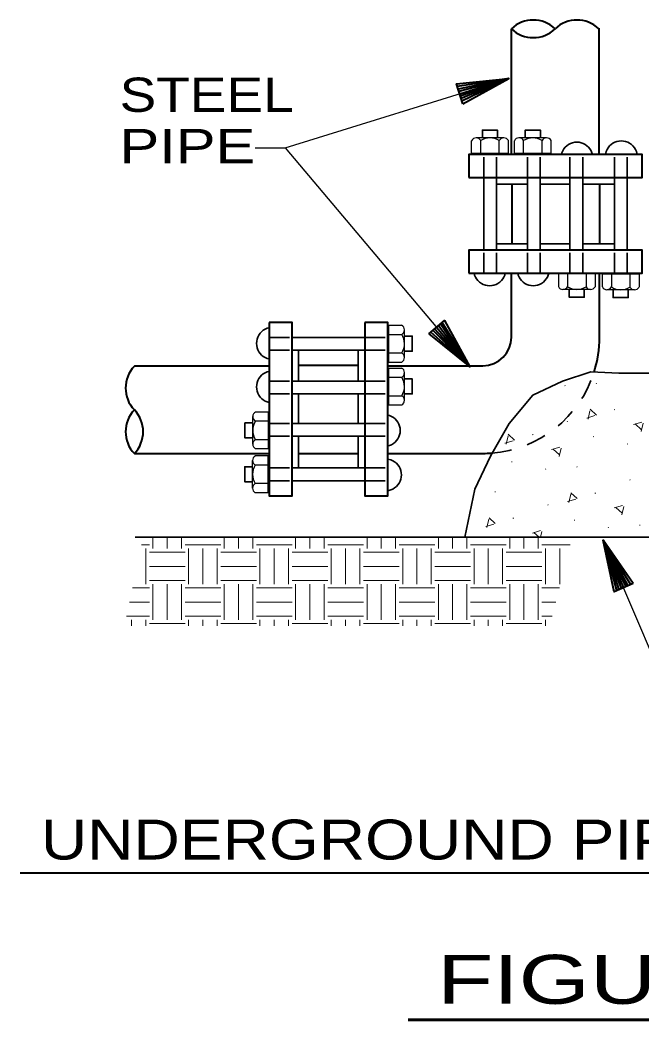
# Model space of a CAD drawing. Extents: x 55 to 190, y 198 to 264.
# Drawn here: x 91.18 to 95.8, y 210.74 to 218.16 of the extents above; entities that cross this region are included whole.
import ezdxf
from ezdxf.enums import TextEntityAlignment as Align

# ---------------------------------------------------------------- set-up
doc = ezdxf.new("R2010")
doc.units = 0
doc.header["$LTSCALE"] = 0.1
doc.linetypes.add('SHORT_DASHED', pattern=[2.7, 1.5, -1.2])
doc.layers.add('2', color=7, linetype='Continuous', lineweight=40)

msp = doc.modelspace()

# ---------------------------------------------------------------- linework, layer by layer
at = {"layer": '2'}
for p, q in [((94.8281, 217.1625), (94.8281, 218.0939)), ((95.4787, 217.1625), (95.4787, 218.0994)), ((94.8101, 217.7242), (94.4283, 217.6647)), ((94.8101, 217.7242), (94.4391, 217.629)), ((94.4447, 217.6107), (94.8101, 217.7242)), ((94.8101, 217.7242), (94.4502, 217.5938)), ((94.8101, 217.7242), (94.4548, 217.5774)), ((94.8101, 217.7242), (94.4616, 217.557)), ((94.832, 216.94), (94.832, 216.4995)), ((95.4832, 216.4995), (95.4832, 216.94)), ((94.8281, 215.806), (94.8281, 216.2815)), ((95.4816, 215.806), (95.4816, 216.2815)), ((94.5193, 215.5867), (94.2455, 215.8568)), ((94.5193, 215.5867), (94.259, 215.8674)), ((94.2725, 215.879), (94.5193, 215.5867)), ((94.5193, 215.5867), (94.2873, 215.8912)), ((94.5193, 215.5867), (94.3158, 215.9153)), ((94.5193, 215.5867), (94.2296, 215.8425)), ((92.0322, 215.5943), (93.0318, 215.5943)), ((93.6904, 215.5949), (93.2498, 215.5949)), ((93.9129, 215.5943), (94.6164, 215.5943)), ((92.0322, 214.9435), (93.0318, 214.9435)), ((93.2498, 214.9437), (93.6904, 214.9437)), ((93.9129, 214.9435), (94.6164, 214.9435)), ((95.6607, 213.947), (95.5094, 214.2987)), ((95.5094, 214.2987), (95.6927, 213.9605)), ((95.5094, 214.2987), (95.6086, 213.9251)), ((95.5094, 214.2987), (95.643, 213.9399)), ((95.5094, 214.2987), (95.6769, 213.9544)), ((95.5094, 214.2987), (95.7123, 213.9695)), ((91.1842, 211.8314), (100.5701, 211.8314))]:
    msp.add_line(p, q, dxfattribs=at)
at = {"layer": '2', "lineweight": 25}
for p, q in [((94.5328, 217.1694), (94.5328, 217.2636)), ((94.7712, 217.285), (94.5669, 217.285)), ((94.6008, 217.1694), (94.6008, 217.2644)), ((94.7379, 217.1694), (94.7379, 217.2644)), ((94.8056, 217.1694), (94.8056, 217.2644)), ((94.8506, 217.1694), (94.8506, 217.2636)), ((95.089, 217.285), (94.8847, 217.285)), ((94.9186, 217.1694), (94.9186, 217.2644)), ((95.0556, 217.1694), (95.0556, 217.2644)), ((95.1233, 217.1694), (95.1233, 217.2644)), ((93.1511, 217.2112), (94.5193, 215.5867)), ((94.8056, 217.1694), (94.5328, 217.1694)), ((95.1233, 217.1694), (94.8506, 217.1694)), ((95.4493, 216.2754), (95.1765, 216.2754)), ((95.1765, 216.2754), (95.1765, 216.1812)), ((95.2445, 216.2754), (95.2445, 216.1804)), ((95.3816, 216.2754), (95.3816, 216.1804)), ((95.4493, 216.2754), (95.4493, 216.1804)), ((95.775, 216.2735), (95.5022, 216.2735)), ((95.5022, 216.2735), (95.5022, 216.1793)), ((95.5702, 216.2735), (95.5702, 216.1785)), ((95.7073, 216.2735), (95.7073, 216.1785)), ((95.775, 216.2735), (95.775, 216.1785)), ((95.4149, 216.1597), (95.2107, 216.1597)), ((95.7406, 216.1579), (95.5364, 216.1579)), ((93.9198, 215.6213), (93.9198, 215.8941)), ((93.9198, 215.8941), (94.014, 215.8941)), ((94.0354, 215.6557), (94.0354, 215.86)), ((93.9198, 215.8261), (94.0148, 215.8261)), ((93.9198, 215.6891), (94.0148, 215.6891)), ((93.9198, 215.6213), (94.0148, 215.6213)), ((93.9198, 215.3036), (93.9198, 215.5763)), ((93.9198, 215.5763), (94.014, 215.5763)), ((93.9198, 215.5083), (94.0148, 215.5083)), ((94.0354, 215.338), (94.0354, 215.5422)), ((93.9198, 215.3713), (94.0148, 215.3713)), ((93.9198, 215.3036), (94.0148, 215.3036)), ((92.9101, 215.012), (92.9101, 215.2162)), ((93.0257, 215.2504), (92.9315, 215.2504)), ((93.0257, 214.9776), (93.0257, 215.2504)), ((93.0257, 215.1824), (92.9308, 215.1824)), ((93.0257, 215.0453), (92.9308, 215.0453)), ((93.0257, 214.9776), (92.9308, 214.9776)), ((92.9083, 214.6863), (92.9083, 214.8905)), ((93.0239, 214.9247), (92.9297, 214.9247)), ((93.0239, 214.6519), (93.0239, 214.9247)), ((93.0239, 214.8567), (92.9289, 214.8567)), ((93.0239, 214.7196), (92.9289, 214.7196)), ((93.0239, 214.6519), (92.9289, 214.6519))]:
    msp.add_line(p, q, dxfattribs=at)
at = {"layer": '2', "linetype": 'SHORT_DASHED', "lineweight": 35}
for p, q in [((94.6238, 216.9916), (94.6238, 217.1625)), ((94.7183, 216.9916), (94.7183, 217.1625)), ((94.9471, 216.9916), (94.9471, 217.1625)), ((95.0416, 216.9916), (95.0416, 217.1625)), ((95.2623, 216.9916), (95.2623, 217.1625)), ((95.3567, 216.9916), (95.3567, 217.1625)), ((95.5917, 216.9916), (95.5917, 217.1625)), ((95.6861, 216.9916), (95.6861, 217.1625)), ((94.6238, 216.282), (94.6238, 216.4529)), ((94.7183, 216.282), (94.7183, 216.4529)), ((94.9471, 216.282), (94.9471, 216.4529)), ((95.0416, 216.282), (95.0416, 216.4529)), ((95.2623, 216.282), (95.2623, 216.4529)), ((95.3567, 216.282), (95.3567, 216.4529)), ((95.5917, 216.282), (95.5917, 216.4529)), ((95.6861, 216.282), (95.6861, 216.4529)), ((93.0324, 215.8031), (93.2033, 215.8031)), ((93.742, 215.8031), (93.9129, 215.8031)), ((93.0324, 215.7086), (93.2033, 215.7086)), ((93.742, 215.7086), (93.9129, 215.7086)), ((93.0324, 215.4798), (93.2033, 215.4798)), ((93.742, 215.4798), (93.9129, 215.4798)), ((93.0324, 215.3853), (93.2033, 215.3853)), ((93.742, 215.3853), (93.9129, 215.3853)), ((93.0324, 215.1646), (93.2033, 215.1646)), ((93.742, 215.1646), (93.9129, 215.1646)), ((93.0324, 215.0702), (93.2033, 215.0702)), ((93.742, 215.0702), (93.9129, 215.0702)), ((93.0324, 214.8352), (93.2033, 214.8352)), ((93.742, 214.8352), (93.9129, 214.8352)), ((93.0324, 214.7408), (93.2033, 214.7408)), ((93.742, 214.7408), (93.9129, 214.7408))]:
    msp.add_line(p, q, dxfattribs=at)
at = {"layer": '2', "lineweight": 35}
for p, q in [((94.6238, 216.4524), (94.6238, 216.9916)), ((94.7183, 216.4524), (94.7183, 216.9916)), ((94.9471, 216.4524), (94.9471, 216.9916)), ((95.0416, 216.4524), (95.0416, 216.9916)), ((95.2623, 216.9916), (95.2623, 216.4524)), ((95.3567, 216.9916), (95.3567, 216.4524)), ((95.5917, 216.9916), (95.5917, 216.4524)), ((95.6861, 216.9916), (95.6861, 216.4524)), ((94.9463, 216.9403), (94.7183, 216.9403)), ((95.2625, 216.9403), (95.0413, 216.9403)), ((95.5917, 216.9403), (95.3575, 216.9403)), ((94.7183, 216.4979), (94.9463, 216.4979)), ((95.0413, 216.4979), (95.2625, 216.4979)), ((95.3575, 216.4979), (95.5917, 216.4979)), ((93.2027, 215.8031), (93.742, 215.8031)), ((93.2027, 215.7086), (93.742, 215.7086)), ((93.2483, 215.7086), (93.2483, 215.4806)), ((93.6906, 215.4806), (93.6906, 215.7086)), ((93.2027, 215.4798), (93.742, 215.4798)), ((93.2027, 215.3853), (93.742, 215.3853)), ((93.2483, 215.3856), (93.2483, 215.1644)), ((93.6906, 215.1644), (93.6906, 215.3856)), ((93.742, 215.1646), (93.2027, 215.1646)), ((93.742, 215.0702), (93.2027, 215.0702)), ((93.2483, 215.0694), (93.2483, 214.8352)), ((93.6906, 214.8352), (93.6906, 215.0694)), ((93.742, 214.8352), (93.2027, 214.8352)), ((93.742, 214.7408), (93.2027, 214.7408)), ((92.0375, 214.3211), (98.441, 214.3211))]:
    msp.add_line(p, q, dxfattribs=at)
at = {"layer": '2', "lineweight": 13}
for p, q in [((95.2271, 215.4443), (95.2234, 215.4478)), ((95.4583, 215.4652), (95.4573, 215.4602)), ((95.4107, 215.2591), (95.3964, 215.1972)), ((95.4594, 215.2276), (95.4131, 215.271)), ((95.5898, 215.2668), (95.5956, 215.2686)), ((95.3871, 215.2049), (95.448, 215.2236)), ((95.2416, 215.1787), (95.2429, 215.1837)), ((95.7946, 215.176), (95.7337, 215.1575)), ((95.7451, 215.1617), (95.7917, 215.1186)), ((95.7898, 215.1064), (95.8041, 215.1683)), ((94.7799, 215.0194), (94.8408, 215.0379)), ((94.8032, 215.0736), (94.7889, 215.0117)), ((94.8519, 215.0416), (94.8053, 215.085)), ((94.9823, 215.0813), (94.9884, 215.0832)), ((95.4403, 215.0678), (95.4353, 215.0662)), ((95.1874, 214.9903), (95.1265, 214.9718)), ((95.1376, 214.9757), (95.1842, 214.9326)), ((95.1821, 214.921), (95.1964, 214.9826)), ((95.6917, 215.0112), (95.6877, 215.0149)), ((94.8331, 214.8821), (94.8281, 214.8805)), ((95.0842, 214.8252), (95.0802, 214.8289)), ((95.3157, 214.8466), (95.3144, 214.8413)), ((95.7065, 214.7455), (95.7076, 214.7506)), ((94.7079, 214.6611), (94.7066, 214.6559)), ((95.2445, 214.586), (95.3054, 214.6045)), ((95.2681, 214.6402), (95.2538, 214.5786)), ((95.3162, 214.6088), (95.2699, 214.6519)), ((95.4469, 214.6477), (95.453, 214.6495)), ((95.0987, 214.5598), (95.1001, 214.5651)), ((95.6517, 214.5569), (95.5911, 214.5384)), ((95.6022, 214.5429), (95.6485, 214.4995)), ((95.647, 214.4876), (95.6613, 214.5495)), ((94.6603, 214.4548), (94.646, 214.3929)), ((94.7087, 214.4227), (94.6622, 214.4661)), ((94.8397, 214.4622), (94.8458, 214.464)), ((95.2975, 214.4487), (95.2924, 214.4471)), ((94.6373, 214.4003), (94.6979, 214.4188)), ((95.0445, 214.3712), (94.9839, 214.3526)), ((95.5485, 214.3921), (95.5446, 214.3958)), ((95.7803, 214.4135), (95.7793, 214.4082)), ((92.1698, 214.2375), (92.1698, 214.3246)), ((92.2756, 214.2375), (92.2756, 214.3246)), ((92.3815, 214.2375), (92.3815, 214.3246)), ((92.699, 214.2375), (92.699, 214.3246)), ((92.8048, 214.2375), (92.8048, 214.3246)), ((92.9106, 214.2375), (92.9106, 214.3246)), ((93.2281, 214.2375), (93.2281, 214.3246)), ((93.334, 214.2375), (93.334, 214.3246)), ((93.4398, 214.2375), (93.4398, 214.3246)), ((93.7573, 214.2375), (93.7573, 214.3246)), ((93.8631, 214.2375), (93.8631, 214.3246)), ((93.969, 214.2375), (93.969, 214.3246)), ((94.2865, 214.2375), (94.2865, 214.3246)), ((94.3923, 214.2375), (94.3923, 214.3246)), ((94.4981, 214.2375), (94.4981, 214.3246)), ((94.8156, 214.2375), (94.8156, 214.3246)), ((94.9215, 214.2375), (94.9215, 214.3246)), ((94.9945, 214.3569), (95.0329, 214.3211)), ((95.0273, 214.2375), (95.0273, 214.3246)), ((95.0437, 214.3211), (95.0535, 214.364)), ((92.0851, 214.264), (92.1434, 214.264)), ((92.1169, 213.973), (92.1169, 214.2375)), ((92.4079, 214.264), (92.6725, 214.264)), ((92.4344, 213.973), (92.4344, 214.2375)), ((92.5402, 213.973), (92.5402, 214.2375)), ((92.6461, 213.973), (92.6461, 214.2375)), ((92.9371, 214.264), (93.2017, 214.264)), ((92.9636, 213.973), (92.9636, 214.2375)), ((93.0694, 213.973), (93.0694, 214.2375)), ((93.1752, 213.973), (93.1752, 214.2375)), ((93.4663, 214.264), (93.7308, 214.264)), ((93.4927, 213.973), (93.4927, 214.2375)), ((93.5986, 213.973), (93.5986, 214.2375)), ((93.7044, 213.973), (93.7044, 214.2375)), ((93.9954, 214.264), (94.26, 214.264)), ((94.0219, 213.973), (94.0219, 214.2375)), ((94.1277, 213.973), (94.1277, 214.2375)), ((94.2336, 213.973), (94.2336, 214.2375)), ((94.5246, 214.264), (94.7892, 214.264)), ((94.5511, 213.973), (94.5511, 214.2375)), ((94.6569, 213.973), (94.6569, 214.2375)), ((94.7627, 213.973), (94.7627, 214.2375)), ((95.0538, 214.264), (95.2633, 214.264)), ((95.0802, 213.973), (95.0802, 214.2375)), ((95.1861, 213.973), (95.1861, 214.2375)), ((92.1434, 214.2111), (92.4079, 214.2111)), ((92.6725, 214.2111), (92.9371, 214.2111)), ((93.2017, 214.2111), (93.4663, 214.2111)), ((93.7308, 214.2111), (93.9954, 214.2111)), ((94.26, 214.2111), (94.5246, 214.2111)), ((94.7892, 214.2111), (95.0538, 214.2111)), ((92.1434, 214.1053), (92.4079, 214.1053)), ((92.6725, 214.1053), (92.9371, 214.1053)), ((93.2017, 214.1053), (93.4663, 214.1053)), ((93.7308, 214.1053), (93.9954, 214.1053)), ((94.26, 214.1053), (94.5246, 214.1053)), ((94.7892, 214.1053), (95.0538, 214.1053)), ((92.1434, 213.9994), (92.4079, 213.9994)), ((92.6725, 213.9994), (92.9371, 213.9994)), ((93.2017, 213.9994), (93.4663, 213.9994)), ((93.7308, 213.9994), (93.9954, 213.9994)), ((94.26, 213.9994), (94.5246, 213.9994)), ((94.7892, 213.9994), (95.0538, 213.9994)), ((92.0187, 213.9465), (92.1434, 213.9465)), ((92.1698, 213.7084), (92.1698, 213.973)), ((92.2756, 213.7084), (92.2756, 213.973)), ((92.3815, 213.7084), (92.3815, 213.973)), ((92.4079, 213.9465), (92.6725, 213.9465)), ((92.699, 213.7084), (92.699, 213.973)), ((92.8048, 213.7084), (92.8048, 213.973)), ((92.9106, 213.7084), (92.9106, 213.973)), ((92.9371, 213.9465), (93.2017, 213.9465)), ((93.2281, 213.7084), (93.2281, 213.973)), ((93.334, 213.7084), (93.334, 213.973)), ((93.4398, 213.7084), (93.4398, 213.973)), ((93.4663, 213.9465), (93.7308, 213.9465)), ((93.7573, 213.7084), (93.7573, 213.973)), ((93.8631, 213.7084), (93.8631, 213.973)), ((93.969, 213.7084), (93.969, 213.973)), ((93.9954, 213.9465), (94.26, 213.9465)), ((94.2865, 213.7084), (94.2865, 213.973)), ((94.3923, 213.7084), (94.3923, 213.973)), ((94.4981, 213.7084), (94.4981, 213.973)), ((94.5246, 213.9465), (94.7892, 213.9465)), ((94.8156, 213.7084), (94.8156, 213.973)), ((94.9215, 213.7084), (94.9215, 213.973)), ((95.0273, 213.7084), (95.0273, 213.973)), ((95.0538, 213.9465), (95.1839, 213.9465)), ((91.9965, 213.8407), (92.1434, 213.8407)), ((92.4079, 213.8407), (92.6725, 213.8407)), ((92.9371, 213.8407), (93.2017, 213.8407)), ((93.4663, 213.8407), (93.7308, 213.8407)), ((93.9954, 213.8407), (94.26, 213.8407)), ((94.5246, 213.8407), (94.7892, 213.8407)), ((95.0538, 213.8407), (95.1575, 213.8407)), ((91.9743, 213.7348), (92.1434, 213.7348)), ((92.0111, 213.6639), (92.0111, 213.7084)), ((92.1169, 213.6639), (92.1169, 213.7084)), ((92.4079, 213.7348), (92.6725, 213.7348)), ((92.4344, 213.6639), (92.4344, 213.7084)), ((92.5402, 213.6639), (92.5402, 213.7084)), ((92.6461, 213.6639), (92.6461, 213.7084)), ((92.9371, 213.7348), (93.2017, 213.7348)), ((92.9636, 213.6639), (92.9636, 213.7084)), ((93.0694, 213.6639), (93.0694, 213.7084)), ((93.1752, 213.6639), (93.1752, 213.7084)), ((93.4663, 213.7348), (93.7308, 213.7348)), ((93.4927, 213.6639), (93.4927, 213.7084)), ((93.5986, 213.6639), (93.5986, 213.7084)), ((93.7044, 213.6639), (93.7044, 213.7084)), ((93.9954, 213.7348), (94.26, 213.7348)), ((94.0219, 213.6639), (94.0219, 213.7084)), ((94.1277, 213.6639), (94.1277, 213.7084)), ((94.2336, 213.6639), (94.2336, 213.7084)), ((94.5246, 213.7348), (94.7892, 213.7348)), ((94.5511, 213.6639), (94.5511, 213.7084)), ((94.6569, 213.6639), (94.6569, 213.7084)), ((94.7627, 213.6639), (94.7627, 213.7084)), ((95.0538, 213.7348), (95.131, 213.7348)), ((95.0802, 213.6639), (95.0802, 213.7084)), ((92.1434, 213.6819), (92.4079, 213.6819)), ((92.6725, 213.6819), (92.9371, 213.6819)), ((93.2017, 213.6819), (93.4663, 213.6819)), ((93.7308, 213.6819), (93.9954, 213.6819)), ((94.26, 213.6819), (94.5246, 213.6819)), ((94.7892, 213.6819), (95.0538, 213.6819))]:
    msp.add_line(p, q, dxfattribs=at)
at = {"layer": '2', "lineweight": 60}
msp.add_line((94.0616, 210.7392), (97.9168, 210.7392), dxfattribs=at)
at = {"layer": '2', "lineweight": 25}
for points in [[(92.9289, 217.2112), (93.1511, 217.2112), (94.8101, 217.7242)], [(96.2105, 213.3411), (95.9198, 213.3411), (95.5094, 214.2987)]]:
    msp.add_lwpolyline(points, dxfattribs=at)
at = {"layer": '2'}
for points in [[(94.4672, 217.5385), (94.4222, 217.6848), (94.8101, 217.7242)], [(94.4672, 217.5385), (94.8101, 217.7242), (94.4333, 217.647)], [(94.2148, 215.8301), (94.332, 215.9285), (94.5193, 215.5867)], [(94.2148, 215.8301), (94.5193, 215.5867), (94.3016, 215.9036)], [(95.73, 213.9772), (95.5893, 213.9171), (95.5094, 214.2987)], [(95.73, 213.9772), (95.5094, 214.2987), (95.6255, 213.9322)]]:
    msp.add_lwpolyline(points, dxfattribs=at)
at = {"layer": '2', "lineweight": 35}
for points in [[(94.613, 217.2855), (94.613, 217.343), (94.7249, 217.343), (94.7249, 217.2855)], [(94.9307, 217.2855), (94.9307, 217.343), (95.0427, 217.343), (95.0427, 217.2855)], [(95.7602, 217.1625), (95.7547, 217.1834), (95.7483, 217.1982), (95.7398, 217.212), (95.7295, 217.2247), (95.7179, 217.2355), (95.7046, 217.2451), (95.6904, 217.2525), (95.675, 217.258), (95.6591, 217.2612), (95.643, 217.2623), (95.6269, 217.2612), (95.611, 217.258), (95.5959, 217.2525), (95.5813, 217.2451), (95.5681, 217.2355), (95.5565, 217.2247), (95.5462, 217.212), (95.5379, 217.1982), (95.5313, 217.1834), (95.5258, 217.1625)], [(95.4284, 217.1625), (95.4252, 217.1742), (95.4189, 217.189), (95.4104, 217.203), (95.4001, 217.2154), (95.3885, 217.2265), (95.3752, 217.2358), (95.361, 217.2432), (95.3456, 217.2488), (95.3297, 217.2519), (95.3136, 217.2533), (95.2975, 217.2519), (95.2816, 217.2488), (95.2662, 217.2432), (95.2519, 217.2358), (95.2387, 217.2265), (95.2271, 217.2154), (95.2168, 217.203), (95.2086, 217.189), (95.2019, 217.1742), (95.1988, 217.1625)], [(94.5513, 216.2815), (94.5553, 216.2666), (94.5619, 216.2518), (94.5701, 216.238), (94.5804, 216.2254), (94.5921, 216.2143), (94.6053, 216.205), (94.6199, 216.1976), (94.6349, 216.192), (94.6508, 216.1889), (94.6669, 216.1878), (94.6831, 216.1889), (94.699, 216.192), (94.7143, 216.1976), (94.7286, 216.205), (94.7418, 216.2143), (94.7535, 216.2254), (94.7638, 216.238), (94.7722, 216.2518), (94.7786, 216.2666), (94.7826, 216.2815)], [(94.8746, 216.2815), (94.8786, 216.2666), (94.8852, 216.2518), (94.8934, 216.238), (94.9038, 216.2254), (94.9154, 216.2143), (94.9286, 216.205), (94.9432, 216.1976), (94.9582, 216.192), (94.9741, 216.1889), (94.9903, 216.1878), (95.0064, 216.1889), (95.0223, 216.192), (95.0376, 216.1976), (95.0519, 216.205), (95.0651, 216.2143), (95.0768, 216.2254), (95.0871, 216.238), (95.0956, 216.2518), (95.1019, 216.2666), (95.1059, 216.2815)], [(95.2567, 216.1592), (95.2567, 216.1018), (95.3686, 216.1018), (95.3686, 216.1592)], [(95.5824, 216.1574), (95.5824, 216.0999), (95.6943, 216.0999), (95.6943, 216.1574)], [(93.0318, 215.8756), (93.017, 215.8716), (93.0022, 215.865), (92.9884, 215.8568), (92.9757, 215.8465), (92.9646, 215.8348), (92.9554, 215.8216), (92.9479, 215.8071), (92.9424, 215.792), (92.9392, 215.7761), (92.9382, 215.76), (92.9392, 215.7438), (92.9424, 215.7279), (92.9479, 215.7126), (92.9554, 215.6983), (92.9646, 215.6851), (92.9757, 215.6734), (92.9884, 215.6631), (93.0022, 215.6547), (93.017, 215.6483), (93.0318, 215.6443)], [(94.0359, 215.8139), (94.0933, 215.8139), (94.0933, 215.702), (94.0359, 215.702)], [(93.0318, 215.5523), (93.017, 215.5483), (93.0022, 215.5417), (92.9884, 215.5335), (92.9757, 215.5232), (92.9646, 215.5115), (92.9554, 215.4983), (92.9479, 215.4837), (92.9424, 215.4687), (92.9392, 215.4528), (92.9382, 215.4366), (92.9392, 215.4205), (92.9424, 215.4046), (92.9479, 215.3893), (92.9554, 215.375), (92.9646, 215.3618), (92.9757, 215.3501), (92.9884, 215.3398), (93.0022, 215.3313), (93.017, 215.325), (93.0318, 215.321)], [(94.0359, 215.4962), (94.0933, 215.4962), (94.0933, 215.3843), (94.0359, 215.3843)], [(96.7643, 214.3296), (96.6598, 214.6664), (96.5783, 214.8641), (96.4621, 215.0384), (96.3693, 215.2361), (96.1949, 215.3755), (95.8928, 215.5382), (95.6255, 215.5382), (95.4162, 215.5496), (95.207, 215.48), (94.9863, 215.3755), (94.8119, 215.1662), (94.6725, 214.9223), (94.5564, 214.6781), (94.4823, 214.3211)], [(93.9129, 214.9985), (93.9245, 215.0017), (93.9393, 215.008), (93.9534, 215.0165), (93.9658, 215.0268), (93.9769, 215.0384), (93.9862, 215.0517), (93.9936, 215.066), (93.9991, 215.0813), (94.0023, 215.0972), (94.0036, 215.1133), (94.0023, 215.1295), (93.9991, 215.1453), (93.9936, 215.1607), (93.9862, 215.175), (93.9769, 215.1882), (93.9658, 215.1998), (93.9534, 215.2102), (93.9393, 215.2184), (93.9245, 215.225), (93.9129, 215.2281)], [(92.9096, 215.1702), (92.8522, 215.1702), (92.8522, 215.0583), (92.9096, 215.0583)], [(93.9129, 214.6667), (93.9338, 214.6723), (93.9486, 214.6786), (93.9624, 214.6871), (93.9751, 214.6974), (93.9859, 214.709), (93.9954, 214.7223), (94.0028, 214.7366), (94.0084, 214.7519), (94.0116, 214.7678), (94.0126, 214.7839), (94.0116, 214.8), (94.0084, 214.8159), (94.0028, 214.831), (93.9954, 214.8456), (93.9859, 214.8588), (93.9751, 214.8704), (93.9624, 214.8808), (93.9486, 214.889), (93.9338, 214.8956), (93.9129, 214.9011)], [(92.9077, 214.8445), (92.8503, 214.8445), (92.8503, 214.7326), (92.9077, 214.7326)]]:
    msp.add_lwpolyline(points, dxfattribs=at)
at = {"layer": '2'}
for points in [[(94.5114, 216.9916), (95.7983, 216.9916), (95.7983, 217.1625), (94.5114, 217.1625)], [(94.5114, 216.2815), (95.7983, 216.2815), (95.7983, 216.4524), (94.5114, 216.4524)], [(93.0318, 215.9155), (93.0318, 214.6286), (93.2027, 214.6286), (93.2027, 215.9155)], [(93.742, 215.9155), (93.742, 214.6286), (93.9129, 214.6286), (93.9129, 215.9155)]]:
    msp.add_lwpolyline(points, close=True, dxfattribs=at)
for centre, radius, start, end in [((94.9901, 217.9262), 0.2331, 45.9775, 134.02119), ((95.3142, 217.9262), 0.2331, 45.97881, 134.0225), ((94.9901, 218.2615), 0.2331, 225.97881, 314.0225), ((94.6164, 215.806), 0.2117, 270, 0), ((94.6164, 215.8086), 0.8652, 342.3994, 359.82419), ((92.1999, 215.4285), 0.2331, 135.97881, 224.0225), ((92.1999, 215.1044), 0.2331, 135.9775, 224.02119), ((91.8646, 215.1044), 0.2331, 315.97881, 44.0225), ((94.6164, 215.8086), 0.8652, 270, 274.36646)]:
    msp.add_arc(centre, radius, start, end, dxfattribs=at)
at = {"layer": '2', "lineweight": 25}
for centre, radius, start, end in [((94.5671, 217.2466), 0.0382, 28.1609, 153.21731), ((94.6694, 217.159), 0.126, 57.05703, 122.99384), ((94.7717, 217.2469), 0.0382, 27.96581, 152.1123), ((94.8848, 217.2466), 0.0382, 28.1609, 153.21731), ((94.9872, 217.159), 0.126, 57.05703, 122.99384), ((95.0894, 217.2469), 0.0382, 27.96581, 152.1123), ((95.2108, 216.1981), 0.0382, 206.78269, 331.8391), ((95.3131, 216.2858), 0.126, 237.00616, 302.94298), ((95.4154, 216.1979), 0.0382, 207.8877, 332.03419), ((95.5365, 216.1963), 0.0382, 206.78269, 331.8391), ((95.6388, 216.2839), 0.126, 237.00616, 302.94298), ((95.7411, 216.196), 0.0382, 207.8877, 332.03419), ((93.997, 215.8598), 0.0382, 298.1609, 63.21731), ((93.9094, 215.7575), 0.126, 327.05703, 32.99384), ((93.9973, 215.6552), 0.0382, 297.96581, 62.1123), ((93.997, 215.5421), 0.0382, 298.1609, 63.21731), ((93.9094, 215.4397), 0.126, 327.05703, 32.99384), ((93.9973, 215.3375), 0.0382, 297.96581, 62.1123), ((92.9485, 215.2161), 0.0382, 116.78269, 241.8391), ((93.0361, 215.1138), 0.126, 147.00616, 212.94297), ((92.9482, 215.0115), 0.0382, 117.8877, 242.03419), ((92.9467, 214.8904), 0.0382, 116.78269, 241.8391), ((93.0343, 214.7881), 0.126, 147.00616, 212.94297), ((92.9464, 214.6858), 0.0382, 117.8877, 242.03419)]:
    msp.add_arc(centre, radius, start, end, dxfattribs=at)
at = {"layer": '2', "linetype": 'SHORT_DASHED', "lineweight": 35}
msp.add_arc((94.6164, 215.8086), 0.8652, 274.36646, 342.3994, dxfattribs=at)

# ---------------------------------------------------------------- texts
at = {"layer": '2'}
for s, width, p in [('STEEL', 1.2, (91.9227, 217.4779)), ('PIPE', 1.3, (91.9227, 217.0969))]:
    msp.add_text(s, height=0.254, dxfattribs=dict(at, width=width)).set_placement(p)
for s, height, width, p in [('UNDERGROUND PIPING RISER-ELBOWS', 0.2963, 1.2, (96.0018, 211.9299)), ('FIGURE "N"', 0.3633, 1.4, (96.1437, 210.8593))]:
    msp.add_text(s, height=height, dxfattribs=dict(at, width=width)).set_placement(p, align=Align.CENTER)

doc.saveas('drawing.dxf')
